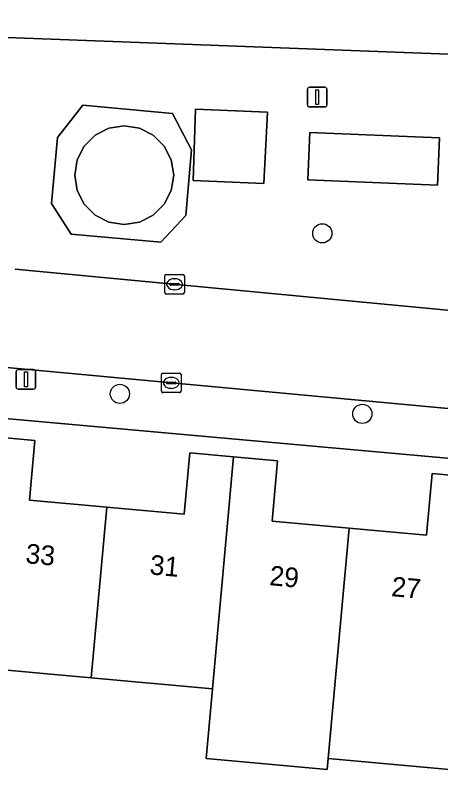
# Model space of a CAD drawing. Extents: x 161354 to 162026, y 386504 to 387460.
# Drawn here: x 161471.21 to 161492.87, y 386914.9 to 386953.74 of the extents above; entities that cross this region are included whole.
import ezdxf

# ---------------------------------------------------------------- set-up
doc = ezdxf.new("R2010")
doc.units = 0
for name, color, linetype in [('IMGEO_Boom', 7, 'Continuous'), ('IMGEO_Erf', 7, 'Continuous'), ('IMGEO_Kolk', 7, 'Continuous'), ('IMGEO_Lichtmast', 7, 'Continuous'), ('IMGEO_Pand', 7, 'Continuous'), ('IMGEO_Pand_nummerreeks', 7, 'Continuous'), ('IMGEO_Rijbaan_lokaal_open', 7, 'Continuous'), ('IMGEO_Terreindeel_open', 7, 'Continuous'), ('IMGEO_Voetpad_open', 7, 'Continuous')]:
    doc.layers.add(name, color=color, linetype=linetype)

msp = doc.modelspace()

# ---------------------------------------------------------------- linework, layer by layer
at = {"layer": 'IMGEO_Boom'}
for centre in [(161486.836, 386942.635), (161476.533, 386934.455), (161488.874, 386933.433)]:
    msp.add_circle(centre, 0.489, dxfattribs=at)
at = {"layer": 'IMGEO_Erf'}
for points in [[(161429.855, 386954.16), (161500, 386951.511), (161502.002, 386951.426)], [(161502.252, 386913.113), (161502.647, 386920.904), (161503.008, 386928.059), (161503.017, 386928.258), (161503.009, 386928.456), (161502.982, 386928.653), (161502.938, 386928.847), (161502.878, 386929.036), (161502.8, 386929.219), (161502.706, 386929.395), (161502.597, 386929.561), (161502.474, 386929.717), (161502.337, 386929.861), (161502.188, 386929.992), (161502.028, 386930.11), (161501.858, 386930.213), (161501.679, 386930.3), (161501.493, 386930.371), (161501.302, 386930.425), (161501.138, 386930.457), (161500, 386930.56), (161439.113, 386936.044)], [(161469.975, 386932.274), (161472.198, 386932.072), (161471.922, 386929.033), (161475.862, 386928.675), (161479.803, 386928.317), (161480.087, 386931.443), (161482.322, 386931.24), (161484.558, 386931.037), (161484.279, 386927.963), (161488.208, 386927.607), (161492.137, 386927.25), (161492.422, 386930.389), (161494.642, 386930.187)], [(161493.292, 386915.317), (161487.143, 386915.876), (161487.091, 386915.308), (161480.926, 386915.868), (161481.249, 386919.42), (161475.073, 386919.98), (161468.91, 386920.54)]]:
    msp.add_lwpolyline(points, dxfattribs=at)
at = {"layer": 'IMGEO_Kolk'}
for p, q in [((161478.813, 386939.612), (161478.813, 386940.464)), ((161478.888, 386940.538), (161479.74, 386940.538)), ((161479.301, 386940.318), (161479.326, 386940.318)), ((161479.814, 386940.464), (161479.814, 386939.612)), ((161479.072, 386940.032), (161479.072, 386940.044)), ((161479.51, 386939.995), (161479.112, 386939.995)), ((161479.115, 386940.081), (161479.513, 386940.081)), ((161479.556, 386940.044), (161479.556, 386940.032)), ((161479.74, 386939.538), (161478.888, 386939.538)), ((161479.324, 386939.758), (161479.299, 386939.758)), ((161478.646, 386934.59), (161478.646, 386935.442)), ((161478.721, 386935.516), (161479.573, 386935.516)), ((161479.134, 386935.296), (161479.159, 386935.296)), ((161479.647, 386935.442), (161479.647, 386934.59)), ((161478.905, 386935.01), (161478.905, 386935.022)), ((161479.343, 386934.973), (161478.945, 386934.973)), ((161478.948, 386935.059), (161479.346, 386935.059)), ((161479.389, 386935.022), (161479.389, 386935.01)), ((161479.573, 386934.516), (161478.721, 386934.516)), ((161479.157, 386934.736), (161479.132, 386934.736))]:
    msp.add_line(p, q, dxfattribs=at)
for points in [[(161478.813, 386939.612), (161478.813, 386940.464)], [(161478.888, 386940.538), (161479.74, 386940.538)], [(161479.814, 386940.464), (161479.814, 386939.612)], [(161479.74, 386939.538), (161478.888, 386939.538)], [(161478.646, 386934.59), (161478.646, 386935.442)], [(161478.721, 386935.516), (161479.573, 386935.516)], [(161479.647, 386935.442), (161479.647, 386934.59)], [(161479.573, 386934.516), (161478.721, 386934.516)]]:
    msp.add_lwpolyline(points, dxfattribs=at)
for centre, radius, start, end in [((161478.89, 386940.462), 0.0765, 91.552, 178.448), ((161478.89, 386940.462), 0.0765, 91.552, 178.448), ((161479.738, 386940.462), 0.0765, 1.552, 88.448), ((161479.738, 386940.462), 0.0765, 1.552, 88.448), ((161479.112, 386940.041), 0.0403, 85.8775, 175.7526), ((161479.109, 386940.031), 0.0366, 178.938, 274.7102), ((161479.513, 386940.038), 0.043, 264.8664, 352.4533), ((161479.517, 386940.043), 0.0386, 1.7309, 96.639), ((161478.89, 386939.614), 0.0765, 181.552, 268.448), ((161478.89, 386939.614), 0.0765, 181.552, 268.448), ((161479.738, 386939.614), 0.0765, 271.552, 358.448), ((161479.738, 386939.614), 0.0765, 271.552, 358.448), ((161478.723, 386935.44), 0.0765, 91.552, 178.448), ((161478.723, 386935.44), 0.0765, 91.552, 178.448), ((161479.571, 386935.44), 0.0765, 1.552, 88.448), ((161479.571, 386935.44), 0.0765, 1.552, 88.448), ((161478.945, 386935.019), 0.0403, 85.8775, 175.7526), ((161478.942, 386935.009), 0.0366, 178.938, 274.7102), ((161479.346, 386935.016), 0.043, 264.8664, 352.4533), ((161479.35, 386935.021), 0.0386, 1.7309, 96.639), ((161478.723, 386934.592), 0.0765, 181.552, 268.448), ((161478.723, 386934.592), 0.0765, 181.552, 268.448), ((161479.571, 386934.592), 0.0765, 271.552, 358.448), ((161479.571, 386934.592), 0.0765, 271.552, 358.448)]:
    msp.add_arc(centre, radius, start, end, dxfattribs=at)
for centre, major_axis, ratio, start_param, end_param in [((161479.3, 386940.038), (-0.387, 0.002), 0.722429, 4.712389, 7.853982), ((161479.325, 386940.038), (-0.39, 0.002), 0.717154, 1.570796, 4.712389), ((161479.133, 386935.016), (-0.387, 0.002), 0.722429, 4.712389, 7.853982), ((161479.158, 386935.016), (-0.39, 0.002), 0.717154, 1.570796, 4.712389)]:
    msp.add_ellipse(centre, major_axis=major_axis, ratio=ratio, start_param=start_param, end_param=end_param, dxfattribs=at)
at = {"layer": 'IMGEO_Lichtmast'}
for p, q in [((161486.08, 386949.173), (161486.08, 386949.973)), ((161486.08, 386949.973), (161486.08, 386949.173)), ((161486.18, 386950.073), (161486.97, 386950.073)), ((161486.97, 386950.073), (161486.18, 386950.073)), ((161487.07, 386949.973), (161487.07, 386949.173)), ((161487.07, 386949.173), (161487.07, 386949.973)), ((161486.97, 386949.073), (161486.18, 386949.073)), ((161486.18, 386949.073), (161486.97, 386949.073)), ((161471.25, 386934.795), (161471.25, 386935.595)), ((161471.25, 386935.595), (161471.25, 386934.795)), ((161471.35, 386935.695), (161472.14, 386935.695)), ((161472.14, 386935.695), (161471.35, 386935.695)), ((161472.24, 386935.595), (161472.24, 386934.795)), ((161472.24, 386934.795), (161472.24, 386935.595)), ((161472.14, 386934.695), (161471.35, 386934.695)), ((161471.35, 386934.695), (161472.14, 386934.695))]:
    msp.add_line(p, q, dxfattribs=at)
for points in [[(161486.5, 386949.948), (161486.65, 386949.948), (161486.65, 386949.198), (161486.5, 386949.198), (161486.5, 386949.948)], [(161471.67, 386935.57), (161471.82, 386935.57), (161471.82, 386934.82), (161471.67, 386934.82), (161471.67, 386935.57)]]:
    msp.add_lwpolyline(points, dxfattribs=at)
for centre, start, end in [((161486.18, 386949.973), 90, 180), ((161486.18, 386949.973), 90, 180), ((161486.97, 386949.973), 0, 90), ((161486.97, 386949.973), 360, 90), ((161486.18, 386949.173), 180, 270), ((161486.18, 386949.173), 180, 270), ((161486.97, 386949.173), 270, 0), ((161486.97, 386949.173), 270, 0), ((161471.35, 386935.595), 90, 180), ((161471.35, 386935.595), 90, 180), ((161472.14, 386935.595), 0, 90), ((161472.14, 386935.595), 360, 90), ((161471.35, 386934.795), 180, 270), ((161471.35, 386934.795), 180, 270), ((161472.14, 386934.795), 270, 0), ((161472.14, 386934.795), 270, 0)]:
    msp.add_arc(centre, 0.1, start, end, dxfattribs=at)
at = {"layer": 'IMGEO_Pand'}
for points in [[(161468.91, 386920.54), (161475.073, 386919.98), (161475.862, 386928.675), (161471.922, 386929.033), (161472.198, 386932.072), (161469.975, 386932.274)], [(161482.322, 386931.24), (161480.087, 386931.443), (161479.803, 386928.317), (161475.862, 386928.675), (161475.073, 386919.98), (161481.249, 386919.42)], [(161488.208, 386927.607), (161484.279, 386927.963), (161484.558, 386931.037), (161482.322, 386931.24), (161481.249, 386919.42), (161480.926, 386915.868), (161487.091, 386915.308), (161487.143, 386915.876), (161487.414, 386918.86)], [(161494.642, 386930.187), (161492.422, 386930.389), (161492.137, 386927.25), (161488.208, 386927.607), (161487.414, 386918.86), (161487.143, 386915.876), (161493.292, 386915.317), (161493.563, 386918.301)]]:
    msp.add_lwpolyline(points, close=True, dxfattribs=at)
at = {"layer": 'IMGEO_Rijbaan_lokaal_open'}
for points in [[(161503.242, 386937.762), (161500, 386938.07), (161471.205, 386940.807)], [(161441.171, 386938.543), (161500, 386933.081), (161503.075, 386932.796), (161503.242, 386937.762)]]:
    msp.add_lwpolyline(points, dxfattribs=at)
at = {"layer": 'IMGEO_Terreindeel_open'}
for points in [[(161483.864, 386945.178), (161484.051, 386948.805), (161480.388, 386948.96), (161480.261, 386945.326)], [(161492.708, 386945.092), (161492.808, 386947.498), (161486.204, 386947.77), (161486.105, 386945.364)]]:
    msp.add_lwpolyline(points, close=True, dxfattribs=at)
at = {"layer": 'IMGEO_Voetpad_open'}
for points in [[(161502.002, 386951.426), (161500, 386951.511), (161429.855, 386954.16), (161428.171, 386954.217), (161404.423, 386955.184)], [(161471.205, 386940.807), (161500, 386938.07), (161503.242, 386937.762), (161504.031, 386953.115), (161504.021, 386953.33)], [(161439.113, 386936.044), (161500, 386930.56), (161501.138, 386930.457), (161501.302, 386930.425), (161501.493, 386930.371), (161501.679, 386930.3), (161501.858, 386930.213), (161502.028, 386930.11), (161502.188, 386929.992), (161502.337, 386929.861), (161502.474, 386929.717), (161502.597, 386929.561), (161502.706, 386929.395), (161502.8, 386929.219), (161502.878, 386929.036), (161502.938, 386928.847), (161502.982, 386928.653), (161503.009, 386928.456), (161503.017, 386928.258), (161503.075, 386932.796), (161500, 386933.081), (161441.171, 386938.543)]]:
    msp.add_lwpolyline(points, dxfattribs=at)
for points in [[(161478.613, 386942.183), (161479.881, 386943.534), (161480.185, 386946.89), (161479.208, 386948.746), (161474.647, 386949.161), (161473.353, 386947.511), (161473.049, 386944.155), (161474.052, 386942.598)], [(161478.613, 386942.183), (161474.052, 386942.598), (161473.049, 386944.155), (161473.353, 386947.511), (161474.647, 386949.161), (161479.208, 386948.746), (161480.185, 386946.89), (161479.881, 386943.534)], [(161483.864, 386945.178), (161480.261, 386945.326), (161480.388, 386948.96), (161484.051, 386948.805)], [(161476.754, 386943.078), (161477.532, 386943.201), (161478.234, 386943.558), (161478.791, 386944.115), (161479.148, 386944.817), (161479.272, 386945.595), (161479.148, 386946.373), (161478.791, 386947.075), (161478.234, 386947.632), (161477.532, 386947.989), (161476.754, 386948.113), (161475.976, 386947.989), (161475.274, 386947.632), (161474.717, 386947.075), (161474.36, 386946.373), (161474.237, 386945.595), (161474.36, 386944.817), (161474.717, 386944.115), (161475.274, 386943.558), (161475.976, 386943.201)], [(161476.754, 386943.078), (161475.976, 386943.201), (161475.274, 386943.558), (161474.717, 386944.115), (161474.36, 386944.817), (161474.237, 386945.595), (161474.36, 386946.373), (161474.717, 386947.075), (161475.274, 386947.632), (161475.976, 386947.989), (161476.754, 386948.113), (161477.532, 386947.989), (161478.234, 386947.632), (161478.791, 386947.075), (161479.148, 386946.373), (161479.272, 386945.595), (161479.148, 386944.817), (161478.791, 386944.115), (161478.234, 386943.558), (161477.532, 386943.201)], [(161486.105, 386945.364), (161486.204, 386947.77), (161492.808, 386947.498), (161492.708, 386945.092)]]:
    msp.add_lwpolyline(points, close=True, dxfattribs=at)

# ---------------------------------------------------------------- texts
at = {"layer": 'IMGEO_Pand_nummerreeks'}
for s, rotation, p in [('33', 354.8329, (161471.703, 386925.833)), ('31', 354.8329, (161478.023, 386925.261)), ('29', 354.8319, (161484.117, 386924.71)), ('27', 354.8319, (161490.324, 386924.149))]:
    msp.add_text(s, height=1, rotation=rotation, dxfattribs=at).set_placement(p)

doc.saveas('drawing.dxf')
